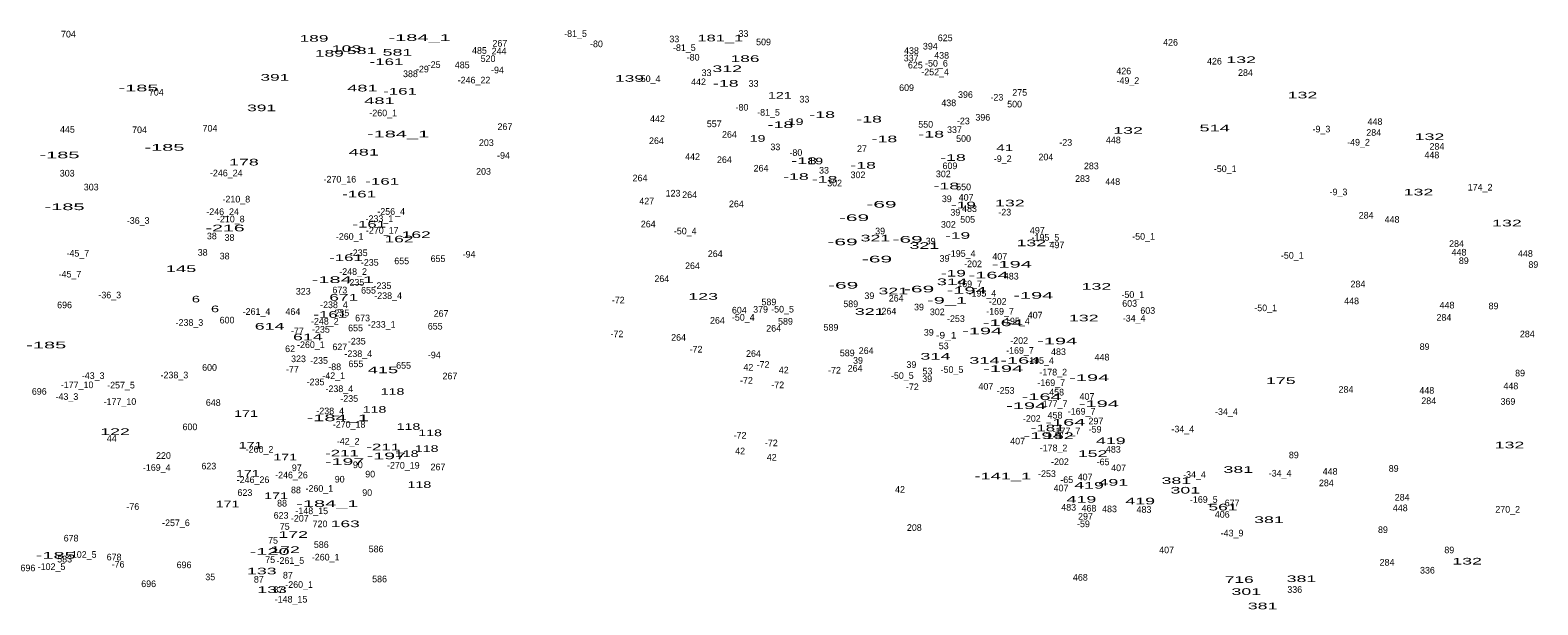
# Model space of a CAD drawing. Extents: x -658595 to -655205, y -1004347 to -1000147.
# Drawn here: x -656989 to -656081, y -1002234 to -1001888 of the extents above; entities that cross this region are included whole.
import ezdxf
from ezdxf.enums import TextEntityAlignment as Align

# ---------------------------------------------------------------- set-up
doc = ezdxf.new("R2010")
doc.units = 0
doc.header["$LTSCALE"] = 1.6
doc.layers.add('24', color=7, linetype='Continuous')

msp = doc.modelspace()

# ---------------------------------------------------------------- texts
at = {"layer": '24'}
for s, p in [('704', (-656965.581, -1001892.3)), ('-81_5', (-656660.366, -1001891.96)), ('33', (-656600.927, -1001895.2)), ('33', (-656559.317, -1001891.93)), ('509', (-656547.217, -1001897)), ('625', (-656437.883, -1001894.53)), ('426', (-656302.257, -1001897.22)), ('485', (-656718.211, -1001902.12)), ('244', (-656706.386, -1001902.49)), ('267', (-656705.908, -1001897.79)), ('-80', (-656647.769, -1001898.15)), ('-81_5', (-656594.886, -1001900.42)), ('-80', (-656589.589, -1001906.22)), ('337', (-656458.363, -1001906.69)), ('438', (-656458.181, -1001902.2)), ('394', (-656446.837, -1001899.55)), ('438', (-656440.011, -1001905.06)), ('-29', (-656752.56, -1001913.34)), ('-25', (-656745.475, -1001910.68)), ('485', (-656728.571, -1001910.86)), ('520', (-656713.021, -1001907.06)), ('-94', (-656707.355, -1001913.9)), ('33', (-656581.527, -1001915.56)), ('625', (-656455.843, -1001910.96)), ('-252_4', (-656443.947, -1001915.07)), ('-50_6', (-656443.152, -1001909.85)), ('426', (-656330.397, -1001914.5)), ('426', (-656275.817, -1001908.6)), ('284', (-656257.151, -1001915.42)), ('388', (-656759.727, -1001916.2)), ('-246_22', (-656721.481, -1001919.98)), ('-50_4', (-656616.061, -1001919.15)), ('442', (-656586.336, -1001921.03)), ('33', (-656553.197, -1001922.03)), ('609', (-656461.132, -1001924.57)), ('-49_2', (-656327.922, -1001920.28)), ('704', (-656912.711, -1001927.3)), ('33', (-656522.617, -1001931.49)), ('438', (-656435.731, -1001933.7)), ('396', (-656425.688, -1001928.7)), ('-23', (-656406.775, -1001930.32)), ('275', (-656393.033, -1001927.43)), ('-260_1', (-656776.136, -1001939.78)), ('-80', (-656560.209, -1001936.37)), ('-81_5', (-656544.206, -1001939.41)), ('396', (-656415.228, -1001942.4)), ('500', (-656396.105, -1001934.46)), ('445', (-656966.186, -1001949.69)), ('704', (-656922.801, -1001949.94)), ('704', (-656880.381, -1001948.99)), ('267', (-656702.858, -1001948.01)), ('442', (-656611.056, -1001943.29)), ('557', (-656576.893, -1001946.33)), ('550', (-656449.611, -1001946.65)), ('337', (-656432.303, -1001949.87)), ('-23', (-656426.945, -1001944.59)), ('-9_3', (-656211.429, -1001949.5)), ('284', (-656179.941, -1001951.57)), ('448', (-656179.186, -1001944.98)), ('203', (-656714.041, -1001957.68)), ('264', (-656611.667, -1001956.52)), ('264', (-656567.737, -1001952.72)), ('33', (-656540.107, -1001960.23)), ('500', (-656426.825, -1001955.21)), ('-23', (-656365.325, -1001957.53)), ('448', (-656336.656, -1001956.05)), ('-49_2', (-656189.112, -1001957.43)), ('284', (-656141.901, -1001959.94)), ('-94', (-656703.715, -1001965.39)), ('442', (-656589.946, -1001966.12)), ('264', (-656570.777, -1001967.94)), ('-80', (-656527.759, -1001963.65)), ('27', (-656487.963, -1001961.31)), ('-9_2', (-656403.239, -1001967.36)), ('204', (-656377.285, -1001966.31)), ('448', (-656144.956, -1001965.12)), ('303', (-656966.331, -1001976.09)), ('-246_24', (-656870.595, -1001975.97)), ('203', (-656715.751, -1001975)), ('264', (-656621.557, -1001978.97)), ('264', (-656548.717, -1001973.08)), ('33', (-656510.817, -1001974.31)), ('302', (-656490.361, -1001977.08)), ('302', (-656439.011, -1001976.5)), ('609', (-656435.022, -1001971.63)), ('283', (-656355.247, -1001979.29)), ('283', (-656349.917, -1001971.68)), ('-50_1', (-656269.36, -1001973.42)), ('303', (-656951.881, -1001984.46)), ('-270_16', (-656802.22, -1001979.71)), ('123', (-656601.699, -1001988.14)), ('302', (-656504.441, -1001982.02)), ('550', (-656426.791, -1001984.32)), ('448', (-656337.046, -1001981.16)), ('-9_3', (-656201.159, -1001987.36)), ('174_2', (-656115.908, -1001984.52)), ('-210_8', (-656864.53, -1001991.72)), ('427', (-656617.517, -1001992.88)), ('264', (-656591.697, -1001989.06)), ('264', (-656563.557, -1001994.57)), ('39', (-656436.923, -1001991.51)), ('407', (-656425.281, -1001990.66)), ('483', (-656423.261, -1001997.41)), ('-36_3', (-656923.598, -1002004.6)), ('-246_24', (-656872.785, -1001999.27)), ('-210_8', (-656867.86, -1002003.7)), ('-233_1', (-656778.436, -1002003.48)), ('-256_4', (-656771.332, -1001999.13)), ('39', (-656431.783, -1001999.69)), ('505', (-656424.361, -1002003.92)), ('-23', (-656402.025, -1001999.57)), ('284', (-656184.501, -1002001.42)), ('448', (-656168.916, -1002003.93)), ('38', (-656879.277, -1002013.92)), ('38', (-656868.637, -1002014.88)), ('-260_1', (-656796.306, -1002014.21)), ('-270_17', (-656776.71, -1002010.56)), ('264', (-656616.617, -1002006.75)), ('-50_4', (-656594.351, -1002010.95)), ('39', (-656477.053, -1002010.91)), ('302', (-656435.971, -1002006.94)), ('497', (-656382.423, -1002010.53)), ('-195_5', (-656377.552, -1002014.77)), ('-50_1', (-656318.48, -1002014.18)), ('-45_7', (-656959.922, -1002024.36)), ('38', (-656884.797, -1002023.82)), ('-235', (-656790.885, -1002024.04)), ('264', (-656576.297, -1002024.63)), ('39', (-656446.623, -1002017)), ('-195_4', (-656427.946, -1002024.48)), ('497', (-656370.613, -1002019.27)), ('284', (-656130.111, -1002018.54)), ('448', (-656128.606, -1002023.71)), ('448', (-656088.666, -1002024.48)), ('38', (-656871.577, -1002026.02)), ('-235', (-656784.225, -1002029.84)), ('655', (-656765.003, -1002028.93)), ('655', (-656743.133, -1002027.6)), ('-94', (-656724.445, -1002024.93)), ('264', (-656589.987, -1002031.86)), ('39', (-656438.253, -1002027.47)), ('-202', (-656421.109, -1002030.71)), ('407', (-656405.031, -1002026.23)), ('-50_1', (-656228.99, -1002025.61)), ('89', (-656125.733, -1002028.82)), ('89', (-656083.893, -1002031.11)), ('-45_7', (-656964.672, -1002036.92)), ('-248_2', (-656794.247, -1002035.36)), ('-235', (-656792.875, -1002041.83)), ('264', (-656608.437, -1002039.66)), ('-169_7', (-656424.062, -1002042.75)), ('483', (-656398.111, -1002038.14)), ('-36_3', (-656940.718, -1002049.5)), ('323', (-656824.257, -1002047.23)), ('673', (-656802.248, -1002046.49)), ('655', (-656784.973, -1002046.62)), ('-235', (-656776.615, -1002043.83)), ('-238_4', (-656773.167, -1002049.87)), ('39', (-656483.513, -1002049.92)), ('264', (-656467.377, -1002051.42)), ('-195_4', (-656415.486, -1002048.45)), ('-50_1', (-656324.96, -1002049.23)), ('284', (-656189.451, -1002042.89)), ('696', (-656967.923, -1002055.46)), ('-261_4', (-656852.386, -1002059.44)), ('464', (-656830.491, -1002059.45)), ('-238_4', (-656805.787, -1002055.39)), ('-235', (-656801.915, -1002060.28)), ('267', (-656741.278, -1002060.61)), ('-72', (-656634.681, -1002052.55)), ('604', (-656561.781, -1002058.62)), ('379', (-656548.998, -1002058.12)), ('589', (-656543.993, -1002053.66)), ('-50_5', (-656535.776, -1002058.03)), ('589', (-656494.743, -1002054.8)), ('264', (-656471.757, -1002059.22)), ('39', (-656453.653, -1002056.76)), ('302', (-656442.631, -1002059.64)), ('-169_7', (-656404.862, -1002059.31)), ('-202', (-656406.279, -1002053.35)), ('603', (-656326.857, -1002054.58)), ('603', (-656315.957, -1002058.81)), ('-50_1', (-656244.99, -1002057.23)), ('448', (-656193.266, -1002053.04)), ('448', (-656135.826, -1002055.6)), ('89', (-656107.853, -1002056.07)), ('-238_3', (-656892.772, -1002066.04)), ('600', (-656870.111, -1002064.62)), ('-248_2', (-656811.267, -1002065.32)), ('655', (-656792.773, -1002069.35)), ('673', (-656788.558, -1002063.32)), ('-233_1', (-656777.006, -1002067.21)), ('655', (-656744.843, -1002068.31)), ('264', (-656574.967, -1002064.78)), ('-50_4', (-656559.411, -1002062.95)), ('264', (-656541.117, -1002069.53)), ('589', (-656534.013, -1002065.36)), ('589', (-656506.623, -1002068.98)), ('-253', (-656431.425, -1002063.72)), ('-195_4', (-656395.326, -1002065.19)), ('407', (-656383.731, -1002061.62)), ('-34_4', (-656324.151, -1002063.47)), ('284', (-656137.721, -1002063.01)), ('-77', (-656827.785, -1002071.15)), ('-235', (-656813.615, -1002070.18)), ('-235', (-656792.025, -1002077.31)), ('-72', (-656635.451, -1002072.91)), ('264', (-656598.357, -1002075.05)), ('39', (-656447.763, -1002071.98)), ('-202', (-656393.349, -1002076.94)), ('284', (-656087.511, -1002072.95)), ('62', (-656832.183, -1002081.89)), ('323', (-656827.107, -1002087.94)), ('-260_1', (-656819.646, -1002079.43)), ('627', (-656802.248, -1002080.72)), ('-238_4', (-656791.137, -1002084.88)), ('-94', (-656745.375, -1002085.63)), ('-72', (-656587.831, -1002082.13)), ('264', (-656553.287, -1002084.75)), ('589', (-656496.833, -1002084.39)), ('264', (-656485.447, -1002083)), ('53', (-656438.767, -1002080.13)), ('-169_7', (-656392.872, -1002082.89)), ('483', (-656369.691, -1002083.66)), ('448', (-656343.506, -1002086.94)), ('89', (-656149.313, -1002080.57)), ('600', (-656880.661, -1002093.16)), ('-77', (-656830.755, -1002094.2)), ('-235', (-656814.755, -1002088.93)), ('-88', (-656805.315, -1002092.75)), ('655', (-656792.573, -1002090.95)), ('655', (-656763.863, -1002091.9)), ('42', (-656556.351, -1002093.03)), ('-72', (-656547.511, -1002091.35)), ('42', (-656535.051, -1002094.75)), ('-72', (-656504.501, -1002094.81)), ('264', (-656492.107, -1002093.65)), ('39', (-656490.363, -1002088.92)), ('39', (-656458.223, -1002091.39)), ('53', (-656448.567, -1002095.35)), ('-50_5', (-656433.806, -1002094.42)), ('-195_4', (-656380.776, -1002088.97)), ('-178_2', (-656372.852, -1002095.96)), ('89', (-656091.873, -1002096.55)), ('-177_10', (-656960.354, -1002103.62)), ('-43_3', (-656950.707, -1002098.09)), ('-257_5', (-656933.938, -1002103.79)), ('-238_3', (-656901.802, -1002097.72)), ('-235', (-656816.845, -1002101.85)), ('-42_1', (-656805.92, -1002098.1)), ('-238_4', (-656802.547, -1002106)), ('267', (-656735.958, -1002098.28)), ('-72', (-656557.501, -1002100.96)), ('-72', (-656538.681, -1002103.64)), ('-50_5', (-656463.696, -1002098.03)), ('-72', (-656457.651, -1002104.8)), ('39', (-656448.713, -1002099.95)), ('407', (-656413.401, -1002104.54)), ('-169_7', (-656374.052, -1002102.3)), ('448', (-656097.416, -1002104.29)), ('696', (-656983.143, -1002107.59)), ('-43_3', (-656966.507, -1002110.67)), ('-177_10', (-656934.584, -1002113.7)), ('648', (-656878.417, -1002114.28)), ('-235', (-656796.595, -1002111.84)), ('-253', (-656401.495, -1002107)), ('-177_7', (-656372.602, -1002114.96)), ('458', (-656370.821, -1002108.02)), ('407', (-656352.541, -1002110.63)), ('284', (-656196.671, -1002106.38)), ('448', (-656147.996, -1002106.97)), ('284', (-656146.851, -1002113.23)), ('369', (-656099.178, -1002113.63)), ('-238_4', (-656808.047, -1002119.34)), ('-202', (-656385.739, -1002123.89)), ('458', (-656371.781, -1002121.9)), ('-169_7', (-656355.782, -1002119.59)), ('-34_4', (-656268.631, -1002119.79)), ('600', (-656892.451, -1002128.93)), ('-270_18', (-656796.665, -1002127.44)), ('-177_7', (-656364.892, -1002131.42)), ('297', (-656347.168, -1002125.44)), ('-59', (-656347.67, -1002130.43)), ('-34_4', (-656294.871, -1002130.25)), ('44', (-656939.486, -1002135.92)), ('-260_2', (-656850.562, -1002142.47)), ('-42_2', (-656797.227, -1002137.61)), ('-72', (-656561.341, -1002133.99)), ('-72', (-656542.521, -1002138.6)), ('407', (-656394.291, -1002137.54)), ('-178_2', (-656372.662, -1002141.62)), ('483', (-656336.671, -1002142.44)), ('220', (-656908.391, -1002146.21)), ('42', (-656561.301, -1002143.45)), ('42', (-656542.281, -1002147.25)), ('-202', (-656368.809, -1002149.94)), ('-65', (-656342.85, -1002150.03)), ('89', (-656228.043, -1002145.87)), ('-169_4', (-656912.451, -1002153.42)), ('623', (-656881.083, -1002152.59)), ('-246_26', (-656854.467, -1002160.8)), ('-246_26', (-656831.357, -1002157.95)), ('97', (-656828.148, -1002153.61)), ('90', (-656802.327, -1002160.47)), ('90', (-656791.387, -1002151.81)), ('90', (-656783.967, -1002157.42)), ('-270_19', (-656764.02, -1002152.12)), ('267', (-656743.178, -1002153.07)), ('-253', (-656376.615, -1002157.14)), ('-65', (-656364.74, -1002160.78)), ('407', (-656353.671, -1002159.15)), ('407', (-656333.521, -1002153.62)), ('-34_4', (-656287.831, -1002157.65)), ('-34_4', (-656236.291, -1002156.88)), ('448', (-656206.196, -1002155.78)), ('89', (-656167.953, -1002154.01)), ('623', (-656859.383, -1002168.53)), ('88', (-656828.657, -1002166.94)), ('-260_1', (-656814.566, -1002166.05)), ('90', (-656785.777, -1002168.55)), ('42', (-656465.071, -1002166.66)), ('407', (-656368.141, -1002165.8)), ('284', (-656208.471, -1002162.7)), ('-76', (-656926.835, -1002176.95)), ('88', (-656837.027, -1002174.93)), ('483', (-656363.551, -1002177.4)), ('468', (-656351.337, -1002177.97)), ('483', (-656338.981, -1002178.36)), ('483', (-656318.241, -1002178.74)), ('-169_5', (-656282.257, -1002172.71)), ('677', (-656265.193, -1002174.81)), ('448', (-656163.976, -1002177.75)), ('284', (-656162.821, -1002171.36)), ('270_2', (-656099.314, -1002178.61)), ('-257_6', (-656900.884, -1002186.74)), ('623', (-656837.593, -1002182.26)), ('-207', (-656826.314, -1002184.01)), ('-148_15', (-656819.143, -1002179.53)), ('720', (-656814.127, -1002187.38)), ('-59', (-656354.68, -1002187.38)), ('297', (-656353.428, -1002182.83)), ('406', (-656271.131, -1002181.68)), ('678', (-656963.978, -1002196)), ('75', (-656835.413, -1002188.97)), ('208', (-656456.461, -1002189.61)), ('-43_9', (-656265.212, -1002192.95)), ('89', (-656174.413, -1002190.92)), ('-102_5', (-656956.99, -1002205.83)), ('75', (-656842.453, -1002197.34)), ('586', (-656813.413, -1002199.87)), ('586', (-656780.413, -1002202.54)), ('407', (-656304.621, -1002203.09)), ('89', (-656134.473, -1002203.09)), ('696', (-656989.983, -1002213.94)), ('-102_5', (-656975.75, -1002213.18)), ('583', (-656967.887, -1002208.64)), ('678', (-656938.108, -1002207.41)), ('-76', (-656935.715, -1002211.75)), ('696', (-656895.993, -1002212.08)), ('75', (-656844.163, -1002208.94)), ('-261_5', (-656832.012, -1002209.49)), ('-260_1', (-656810.776, -1002207.45)), ('284', (-656171.951, -1002210.55)), ('696', (-656917.293, -1002223.49)), ('35', (-656880.227, -1002219.34)), ('87', (-656851.003, -1002220.8)), ('87', (-656833.513, -1002218.32)), ('-260_1', (-656826.756, -1002223.96)), ('586', (-656778.323, -1002220.61)), ('468', (-656356.527, -1002219.62)), ('336', (-656147.623, -1002215.33)), ('87', (-656839.213, -1002226.98)), ('-148_15', (-656831.613, -1002232.81)), ('336', (-656227.503, -1002226.94))]:
    msp.add_text(s, height=4, dxfattribs=at).set_placement(p, align=Align.CENTER)
for s, width, p in [('189', 1.95, (-656817.773, -1001894.87)), ('-184_1', 2.25, (-656754.223, -1001894.37)), ('181_1', 1.85, (-656573.211, -1001894.67)), ('189', 1.95, (-656808.553, -1001903.81)), ('103', 2, (-656798.204, -1001901.06)), ('581', 2, (-656789.107, -1001902.3)), ('581', 2, (-656767.527, -1001903.25)), ('-161', 1.9, (-656774.141, -1001908.94)), ('312', 2, (-656569.077, -1001913.14)), ('186', 1.95, (-656558.333, -1001907.05)), ('132', 2, (-656259.757, -1001907.72)), ('-185', 2.25, (-656923.421, -1001924.76)), ('391', 1.95, (-656841.343, -1001918.36)), ('481', 2.05, (-656788.653, -1001924.83)), ('139', 1.95, (-656627.893, -1001918.99)), ('-18', 2, (-656569.941, -1001921.96)), ('481', 2.05, (-656778.383, -1001932.42)), ('-161', 1.9, (-656765.991, -1001926.71)), ('121', 1.6, (-656537.414, -1001929.15)), ('132', 2, (-656222.857, -1001929.03)), ('391', 1.95, (-656849.323, -1001936.72)), ('-18', 2, (-656511.931, -1001940.78)), ('-18', 2, (-656537.041, -1001946.87)), ('19', 1.6, (-656527.893, -1001945.08)), ('-18', 2, (-656483.671, -1001943.54)), ('132', 2, (-656327.837, -1001950.34)), ('514', 2.05, (-656275.683, -1001948.89)), ('-185', 2.25, (-656907.811, -1001960.56)), ('-184_1', 2.25, (-656767.153, -1001952.48)), ('19', 1.6, (-656550.803, -1001955.16)), ('-18', 2, (-656474.461, -1001955.43)), ('-18', 2, (-656446.321, -1001952.59)), ('41', 1.7, (-656402.043, -1001960.79)), ('132', 2, (-656146.407, -1001954.14)), ('-185', 2.25, (-656970.971, -1001965.1)), ('178', 2, (-656859.973, -1001969.42)), ('481', 2.05, (-656787.793, -1001963.44)), ('-18', 2, (-656522.771, -1001968.57)), ('19', 1.6, (-656516.103, -1001968.76)), ('-18', 2, (-656433.191, -1001966.66)), ('-18', 2, (-656527.721, -1001978.08)), ('-18', 2, (-656487.291, -1001971.32)), ('-161', 1.9, (-656776.741, -1001980.99)), ('-18', 2, (-656510.411, -1001979.78)), ('-18', 2, (-656437.191, -1001983.79)), ('132', 2, (-656153.027, -1001987.51)), ('-185', 2.25, (-656967.911, -1001996.33)), ('-161', 1.9, (-656790.621, -1001988.69)), ('-69', 2.35, (-656476.243, -1001994.82)), ('-19', 1.95, (-656426.935, -1001995.21)), ('132', 2, (-656398.967, -1001994.09)), ('-69', 2.35, (-656492.753, -1002002.89)), ('132', 2, (-656099.767, -1002006.16)), ('-216', 2.2, (-656871.275, -1002009.13)), ('-161', 1.9, (-656784.551, -1002006.81)), ('162', 1.95, (-656756.243, -1002013.13)), ('321', 2, (-656479.897, -1002015.21)), ('-19', 1.95, (-656430.395, -1002013.62)), ('162', 1.95, (-656766.613, -1002015.79)), ('-69', 2.35, (-656499.663, -1002017.49)), ('-69', 2.35, (-656460.493, -1002015.95)), ('321', 2, (-656450.417, -1002019.68)), ('132', 2, (-656386.037, -1002018.07)), ('145', 2.05, (-656897.793, -1002033.66)), ('-161', 1.9, (-656798.511, -1002026.95)), ('-69', 2.35, (-656478.933, -1002027.86)), ('-194', 2.25, (-656397.781, -1002030.98)), ('-184_1', 2.25, (-656800.433, -1002040.25)), ('314', 2.05, (-656433.773, -1002041.54)), ('-19', 1.95, (-656432.965, -1002036.35)), ('-164', 2.25, (-656411.771, -1002037.51)), ('671', 1.95, (-656799.877, -1002050.89)), ('123', 2, (-656583.537, -1002050.35)), ('-69', 2.35, (-656499.283, -1002043.61)), ('321', 2, (-656469.147, -1002047.08)), ('-69', 2.35, (-656453.583, -1002045.91)), ('-194', 2.25, (-656424.981, -1002046.67)), ('-194', 2.25, (-656384.851, -1002049.72)), ('132', 2, (-656346.857, -1002044.32)), ('6', 1.65, (-656888.866, -1002051.96)), ('6', 1.65, (-656877.356, -1002057.85)), ('321', 2, (-656483.317, -1002059.44)), ('-9_1', 2.25, (-656436.757, -1002052.68)), ('614', 2, (-656844.508, -1002068.33)), ('-161', 1.9, (-656808.021, -1002061.2)), ('-164', 2.25, (-656403.211, -1002066.24)), ('132', 2, (-656354.467, -1002063.35)), ('614', 2, (-656821.468, -1002074.77)), ('-9_1', 1.15, (-656437.25, -1002073.72)), ('-194', 2.25, (-656415.661, -1002071.12)), ('-194', 2.25, (-656370.501, -1002077.21)), ('-185', 2.25, (-656978.941, -1002079.66)), ('314', 2.05, (-656443.753, -1002086.41)), ('415', 2.05, (-656776.283, -1002094.61)), ('314', 2.05, (-656414.273, -1002088.89)), ('-194', 2.25, (-656403.021, -1002093.86)), ('-164', 2.25, (-656392.661, -1002088.89)), ('-194', 2.25, (-656351.191, -1002099.29)), ('175', 2, (-656235.863, -1002101.11)), ('118', 1.6, (-656770.514, -1002107.63)), ('-164', 2.25, (-656379.821, -1002110.76)), ('-194', 2.25, (-656345.391, -1002114.98)), ('171', 1.6, (-656858.679, -1002120.9)), ('-184_1', 2.25, (-656803.483, -1002123.51)), ('118', 1.6, (-656781.354, -1002118.46)), ('-194', 2.25, (-656389.131, -1002116.22)), ('122', 2, (-656937.527, -1002131.83)), ('118', 1.6, (-656760.914, -1002128.75)), ('118', 1.6, (-656747.884, -1002132.54)), ('-181', 1.9, (-656376.247, -1002129.6)), ('-164', 2.25, (-656365.551, -1002126.17)), ('171', 1.6, (-656855.939, -1002140)), ('-211', 1.9, (-656776.117, -1002141.07)), ('118', 1.6, (-656749.974, -1002142.04)), ('-194', 2.25, (-656378.671, -1002134.19)), ('152', 2, (-656369.477, -1002134.3)), ('419', 2, (-656338.188, -1002137.33)), ('132', 2, (-656098.247, -1002139.87)), ('171', 1.6, (-656835.099, -1002147.16)), ('-211', 1.9, (-656800.937, -1002144.79)), ('-197', 2.2, (-656799.339, -1002149.87)), ('-197', 2.2, (-656774.239, -1002146.44)), ('118', 1.6, (-656761.964, -1002145.09)), ('152', 2, (-656349.127, -1002145.05)), ('171', 1.6, (-656857.629, -1002156.96)), ('-141_1', 2.05, (-656403.189, -1002158.6)), ('381', 2, (-656261.467, -1002154.65)), ('118', 1.6, (-656754.354, -1002163.73)), ('419', 2, (-656351.298, -1002164.14)), ('491', 2, (-656336.678, -1002162.38)), ('381', 2, (-656298.747, -1002161.31)), ('301', 2, (-656293.354, -1002167.12)), ('171', 1.6, (-656869.799, -1002175.41)), ('171', 1.6, (-656840.609, -1002170.46)), ('-184_1', 2.25, (-656809.763, -1002175.17)), ('419', 2, (-656355.868, -1002172.62)), ('419', 2, (-656320.498, -1002173.66)), ('561', 1.95, (-656270.703, -1002177.3)), ('163', 1.95, (-656798.953, -1002187.37)), ('381', 2, (-656243.017, -1002184.9)), ('172', 2, (-656830.293, -1002193.82)), ('-120', 2.25, (-656844.487, -1002204.02)), ('172', 2, (-656835.233, -1002202.95)), ('-185', 2.25, (-656973.241, -1002206.36)), ('132', 2, (-656123.737, -1002209.88)), ('133', 2, (-656849.197, -1002215.82)), ('716', 1.95, (-656260.877, -1002220.94)), ('381', 2, (-656223.437, -1002220.47)), ('133', 2, (-656843.017, -1002227.05)), ('301', 2, (-656256.654, -1002228.19)), ('381', 2, (-656246.827, -1002236.84))]:
    msp.add_text(s, height=4, dxfattribs=dict(at, width=width)).set_placement(p, align=Align.CENTER)

doc.saveas('drawing.dxf')
